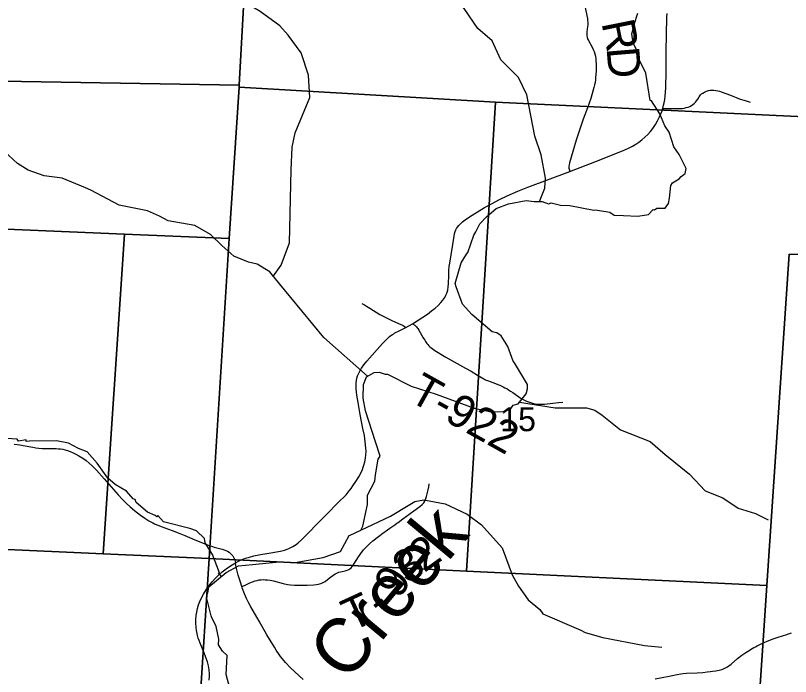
# Model space of a CAD drawing. Extents: x 0 to 34, y 0 to 22.
# Drawn here: x 25.758 to 27.11, y 16.507 to 17.66 of the extents above; entities that cross this region are included whole.
import ezdxf

# ---------------------------------------------------------------- set-up
doc = ezdxf.new("R2010")
doc.units = 0
for name, color, linetype in [('GM_X_County_Road', 7, 'Continuous'), ('GM_X_Minor_River', 7, 'Continuous'), ('GM_X_Minor_River_Text', 7, 'Continuous'), ('GM_X_Section', 7, 'Continuous'), ('GM_X_Section_Text', 7, 'Continuous'), ('GM_X_State_Route', 7, 'Continuous'), ('GM_X_Township_Road', 7, 'Continuous'), ('GM_X_Township_Road_Text', 7, 'Continuous')]:
    doc.layers.add(name, color=color, linetype=linetype)

msp = doc.modelspace()

# ---------------------------------------------------------------- linework, layer by layer
at = {"layer": 'GM_X_County_Road'}
for points in [[(25.7561, 16.9119), (25.7608, 16.9114), (25.7659, 16.9107), (25.7713, 16.9097), (25.7885, 16.9067), (25.7936, 16.9059), (25.799, 16.9052), (25.8046, 16.9048), (25.8103, 16.9046), (25.8291, 16.9044), (25.833, 16.9043), (25.8369, 16.9039), (25.8409, 16.9032), (25.8447, 16.9022), (25.8491, 16.901), (25.8535, 16.8993), (25.8586, 16.8971), (25.8633, 16.8947), (25.8686, 16.8917), (25.8753, 16.8875), (25.8813, 16.8834), (25.8868, 16.8792), (25.8921, 16.8742), (25.8992, 16.867), (25.913, 16.8518), (25.9373, 16.8238), (25.9449, 16.8156), (25.9511, 16.8094), (25.9579, 16.8031), (25.9656, 16.7966), (25.9759, 16.7886), (25.9836, 16.7832), (25.9909, 16.7784), (25.9975, 16.7748), (26.0007, 16.7732), (26.0044, 16.7716), (26.0081, 16.77), (26.0121, 16.7684), (26.0311, 16.7615), (26.0418, 16.7575), (26.0535, 16.7528), (26.074, 16.7442), (26.0957, 16.7355), (26.1019, 16.7334), (26.1044, 16.7325), (26.1071, 16.7318), (26.1188, 16.7288), (26.122, 16.7278), (26.1251, 16.7267), (26.1281, 16.7253), (26.1307, 16.7235), (26.1331, 16.7216), (26.1353, 16.7194), (26.1371, 16.7172), (26.1385, 16.7149), (26.1395, 16.713), (26.1403, 16.7108), (26.141, 16.7084), (26.1416, 16.7049)], [(26.8734, 16.5027), (26.8981, 16.5077), (26.912, 16.5104), (26.9181, 16.5114), (26.9224, 16.512), (26.9285, 16.5125), (26.9471, 16.5133), (26.9565, 16.5139), (26.9645, 16.5148), (26.97, 16.5156), (26.9738, 16.5161), (26.9794, 16.517), (26.985, 16.518), (26.9898, 16.5193), (26.9939, 16.5209), (26.9984, 16.5231), (27.0022, 16.5254), (27.0062, 16.5284), (27.0174, 16.5382), (27.0247, 16.5439), (27.0317, 16.5488), (27.0343, 16.5505), (27.0426, 16.5556), (27.0457, 16.5574), (27.0484, 16.5588), (27.0516, 16.5605), (27.0582, 16.5638), (27.069, 16.5684), (27.0795, 16.5724), (27.0882, 16.5754), (27.103, 16.5803), (27.1041, 16.5807), (27.1112, 16.5831)]]:
    msp.add_lwpolyline(points, dxfattribs=at)
at = {"layer": 'GM_X_Minor_River'}
for points in [[(26.6717, 17.3353), (26.6812, 17.3584), (26.6822, 17.3762), (26.6747, 17.417), (26.664, 17.4496), (26.6499, 17.5215), (26.635, 17.5519), (26.6181, 17.5692), (26.6045, 17.5825), (26.5893, 17.6157), (26.5642, 17.637), (26.5403, 17.6723), (26.4513, 17.7909), (26.4148, 17.8437), (26.3814, 17.8649), (26.3697, 17.8778), (26.3662, 17.887), (26.3625, 17.8917), (26.2809, 17.9664), (26.2609, 18.0039)], [(26.2068, 17.204), (26.2214, 17.2242), (26.236, 17.2634), (26.2386, 17.3906), (26.2407, 17.4301), (26.2458, 17.4552), (26.2716, 17.5168), (26.2691, 17.5559), (26.2564, 17.5946), (26.2338, 17.6256), (26.2189, 17.6418), (26.185, 17.6671), (26.0772, 17.7307), (26.0349, 17.7505), (25.925, 17.7982), (25.8376, 17.8672), (25.8216, 17.8773), (25.7426, 17.8997), (25.7266, 17.9076), (25.6949, 17.9317)], [(26.8364, 17.6413), (26.8368, 17.6439), (26.8432, 17.6637)], [(26.547, 17.2463), (26.5574, 17.2765), (26.5608, 17.2826), (26.5679, 17.2967), (26.5793, 17.3089), (26.5963, 17.3234), (26.6178, 17.3314), (26.6484, 17.3372), (26.6624, 17.3353), (26.6764, 17.3353), (26.6874, 17.3312), (26.6923, 17.3331), (26.7085, 17.3289), (26.7248, 17.3286), (26.7668, 17.3203), (26.7694, 17.3211), (26.7944, 17.317), (26.8023, 17.3117), (26.8186, 17.311), (26.8435, 17.3099), (26.862, 17.313), (26.8703, 17.3213), (26.8726, 17.3206), (26.8764, 17.3236), (26.8911, 17.3237), (26.8968, 17.3317), (26.8987, 17.3412), (26.9009, 17.3632), (26.9039, 17.3682), (26.9157, 17.375), (26.9191, 17.3788), (26.9259, 17.3842), (26.9274, 17.3929), (26.9152, 17.4172), (26.9062, 17.4309), (26.8978, 17.4563), (26.8906, 17.4673), (26.8819, 17.4882), (26.8671, 17.511), (26.8649, 17.5114), (26.8573, 17.5592), (26.8425, 17.5892), (26.8406, 17.601), (26.8353, 17.612), (26.833, 17.6276), (26.8364, 17.6413)], [(26.3718, 17.0307), (26.2957, 17.098), (26.2192, 17.1912), (26.2017, 17.2126), (26.1798, 17.2262), (26.1644, 17.2294), (26.1387, 17.24), (26.1177, 17.2586), (26.0982, 17.2778), (26.0711, 17.2934), (26.0241, 17.3018), (26.0092, 17.3098), (25.9884, 17.3192), (25.9388, 17.3288), (25.8893, 17.355), (25.88, 17.3595), (25.8396, 17.3759), (25.8084, 17.38), (25.78, 17.3903), (25.7618, 17.4019), (25.7313, 17.4298)], [(26.3246, 16.7249), (26.3397, 16.7527), (26.342, 16.7534), (26.3605, 16.7622), (26.3639, 16.7694), (26.3722, 16.8067), (26.3722, 16.8234), (26.3846, 16.8474), (26.3861, 16.8588), (26.3907, 16.8858), (26.3941, 16.8911), (26.3857, 16.9162), (26.3683, 16.9705), (26.3645, 16.9921), (26.3648, 17.0161), (26.3701, 17.0298), (26.3833, 17.037), (26.3924, 17.0378), (26.403, 17.034), (26.4071, 17.0341), (26.448, 17.0133), (26.4919, 16.9993), (26.5577, 16.9751), (26.5875, 16.9688), (26.6087, 16.9692), (26.6212, 16.9734), (26.6257, 16.9799), (26.6344, 16.9825), (26.6487, 16.9997), (26.651, 17.0084), (26.651, 17.016), (26.6283, 17.054), (26.626, 17.057), (26.6165, 17.0825), (26.6052, 17.101), (26.5976, 17.1064), (26.5893, 17.1082), (26.5541, 17.1385), (26.5375, 17.1564), (26.5265, 17.1867), (26.5249, 17.1924), (26.5355, 17.2286), (26.5446, 17.2434), (26.547, 17.2463)], [(26.6369, 16.9856), (26.6991, 16.9758), (26.7539, 16.9756), (26.7682, 16.9713), (26.7811, 16.9626), (26.8132, 16.9369), (26.8648, 16.9166), (26.8913, 16.8941), (26.9337, 16.8597), (26.9608, 16.8308), (26.9915, 16.8188), (27.0181, 16.8005), (27.0485, 16.7912), (27.0704, 16.7802)], [(26.1171, 16.6813), (26.1119, 16.6875), (26.1141, 16.6875), (26.1016, 16.7197), (26.0891, 16.7402), (26.0876, 16.7474), (26.074, 16.7607), (26.0619, 16.7649), (26.0161, 16.7769), (26.0063, 16.7875), (26.0044, 16.7852), (26.0018, 16.7875), (25.9882, 16.7935), (25.9685, 16.8102), (25.9666, 16.8155), (25.9636, 16.817), (25.9515, 16.8303), (25.9318, 16.842), (25.9193, 16.8527), (25.9004, 16.8788), (25.883, 16.8989), (25.8682, 16.9046), (25.8505, 16.9137), (25.8297, 16.9182), (25.7828, 16.9173), (25.7767, 16.9169), (25.7767, 16.9195), (25.7635, 16.9172), (25.7612, 16.9206), (25.7423, 16.9221)], [(26.3605, 16.7622), (26.4122, 16.7868), (26.446, 16.8069), (26.4545, 16.812), (26.4701, 16.8149), (26.5073, 16.808), (26.5457, 16.7901), (26.5705, 16.7715), (26.6067, 16.7312), (26.6245, 16.6843), (26.6352, 16.6642), (26.6519, 16.6409), (26.6726, 16.6239), (26.6776, 16.6162), (26.744, 16.5875), (26.7515, 16.5838), (26.7822, 16.5749), (26.8551, 16.5608), (26.8853, 16.5578)], [(26.147, 16.7001), (26.1712, 16.7024), (26.2181, 16.7071), (26.246, 16.706), (26.2944, 16.7142), (26.3246, 16.7249)], [(26.1317, 16.4865), (26.1253, 16.5104), (26.1271, 16.5435), (26.1192, 16.551), (26.112, 16.562), (26.1127, 16.5723), (26.1078, 16.594), (26.0998, 16.6107), (26.0991, 16.6126), (26.0915, 16.6452), (26.0941, 16.6555), (26.0953, 16.6631), (26.1255, 16.6883), (26.147, 16.7001)]]:
    msp.add_lwpolyline(points, dxfattribs=at)
at = {"layer": 'GM_X_Section'}
for points in [[(26.2062, 18.5294), (27.254, 18.479), (27.228, 18.0601), (27.2029, 17.6387), (27.1952, 17.4804), (26.5953, 17.5088), (26.1481, 17.5351), (26.1482, 17.5386), (26.1578, 17.7173), (26.1806, 18.1307)], [(25.1245, 17.7506), (26.1578, 17.7173), (26.1482, 17.5386), (25.1122, 17.5559)], [(26.1482, 17.5386), (26.1481, 17.5351), (26.131, 17.2706), (25.9484, 17.2784), (25.1664, 17.3116), (25.097, 17.3132), (25.1122, 17.5559)], [(26.5953, 17.5088), (26.5448, 16.6908), (26.0957, 16.7125), (26.131, 17.2706), (26.1481, 17.5351)], [(27.1952, 17.4804), (27.1786, 17.2427), (27.1074, 17.2433), (27.0684, 16.6654), (26.5448, 16.6908), (26.5953, 17.5088)], [(25.9484, 17.2784), (25.9113, 16.7209), (25.1282, 16.7564), (25.1664, 17.3116)], [(26.131, 17.2706), (26.0957, 16.7125), (25.9113, 16.7209), (25.9484, 17.2784)], [(27.1786, 17.2427), (27.1198, 16.4014), (27.0508, 16.4046), (27.0684, 16.6654), (27.1074, 17.2433)], [(25.1282, 16.7564), (25.9113, 16.7209), (26.0957, 16.7125), (26.0791, 16.4497), (25.1102, 16.4936)], [(26.0957, 16.7125), (26.5448, 16.6908), (27.0684, 16.6654), (27.0508, 16.4046), (26.0791, 16.4497)]]:
    msp.add_lwpolyline(points, close=True, dxfattribs=at)
at = {"layer": 'GM_X_State_Route'}
for points in [[(26.1963, 16.7214), (26.2203, 16.7256), (26.227, 16.7273), (26.2306, 16.7285), (26.2359, 16.7305), (26.242, 16.7336), (26.2473, 16.7371), (26.2512, 16.7403), (26.2568, 16.7453), (26.2963, 16.7853), (26.325, 16.8142), (26.33, 16.8193), (26.3345, 16.824), (26.3401, 16.8308), (26.3433, 16.835), (26.3464, 16.8393), (26.3517, 16.8471), (26.3566, 16.855), (26.3602, 16.8616), (26.3631, 16.8679), (26.3646, 16.872), (26.3658, 16.8756), (26.3674, 16.8816), (26.3686, 16.8878), (26.3692, 16.8934), (26.3694, 16.8991), (26.3691, 16.9054), (26.3679, 16.9165), (26.3665, 16.927), (26.364, 16.9392), (26.3592, 16.9641), (26.3554, 16.9848), (26.3544, 16.9911), (26.3534, 16.9974), (26.3527, 17.0036), (26.3524, 17.0085), (26.3521, 17.0141), (26.3522, 17.0189), (26.3526, 17.023), (26.3534, 17.027), (26.3548, 17.0315), (26.3567, 17.036), (26.3589, 17.0406), (26.3615, 17.0449), (26.3654, 17.0504), (26.3708, 17.0571), (26.3982, 17.0879), (26.4019, 17.0919), (26.4054, 17.0953), (26.4081, 17.0978), (26.4105, 17.0998), (26.4129, 17.1016), (26.4155, 17.1034), (26.4176, 17.1048), (26.4198, 17.1061), (26.4222, 17.1073), (26.4248, 17.1086), (26.4389, 17.1157), (26.4507, 17.1222), (26.4765, 17.1391), (26.4837, 17.1445), (26.4897, 17.1494), (26.4951, 17.1543), (26.4998, 17.1591), (26.5034, 17.1632), (26.5067, 17.1679), (26.5087, 17.1718), (26.5102, 17.1753), (26.5119, 17.1807), (26.5127, 17.1863), (26.5131, 17.1919), (26.5135, 17.2067), (26.5137, 17.211), (26.5139, 17.2153), (26.5146, 17.2221), (26.5153, 17.2276), (26.523, 17.2748), (26.5239, 17.2795), (26.5249, 17.283), (26.5259, 17.2858), (26.5274, 17.2885), (26.529, 17.2909), (26.5312, 17.2934), (26.5336, 17.2961), (26.5376, 17.2999), (26.5424, 17.3037), (26.5496, 17.3086), (26.576, 17.3248), (26.588, 17.3314), (26.6023, 17.3387), (26.6157, 17.3452), (26.6339, 17.3532), (26.6517, 17.3603), (26.725, 17.3875), (26.7713, 17.4057), (26.8164, 17.4236), (26.8272, 17.4284), (26.8339, 17.4318), (26.8398, 17.4352), (26.845, 17.4387), (26.8505, 17.4429), (26.8558, 17.4474), (26.8607, 17.4522), (26.8652, 17.4574), (26.8694, 17.4629), (26.8739, 17.4697), (26.8776, 17.4762), (26.8811, 17.4829), (26.8836, 17.4886), (26.8856, 17.4937), (26.8869, 17.4979), (26.8883, 17.5033), (26.8892, 17.5075), (26.8902, 17.5132), (26.8909, 17.5193), (26.8914, 17.5255), (26.892, 17.5345), (26.8924, 17.5438), (26.8926, 17.5522), (26.8928, 17.5628), (26.893, 17.5878), (26.8935, 17.6358), (26.8938, 17.6469), (26.8942, 17.6567), (26.8945, 17.6634)], [(26.1416, 16.7049), (26.1482, 16.7086), (26.1532, 16.7109), (26.159, 16.7131), (26.1661, 16.7151), (26.1739, 16.7171), (26.1854, 16.7195), (26.1963, 16.7214)], [(26.0959, 16.5003), (26.0963, 16.5072), (26.0963, 16.5116), (26.0957, 16.5185), (26.0946, 16.5253), (26.0928, 16.5326), (26.0903, 16.5403), (26.0874, 16.5479), (26.0802, 16.5651), (26.0784, 16.5698), (26.0768, 16.574), (26.0756, 16.5782), (26.0747, 16.5819), (26.074, 16.587), (26.0733, 16.5931), (26.0729, 16.5999), (26.0729, 16.6066), (26.0734, 16.6134), (26.0742, 16.6189), (26.0756, 16.6255), (26.0775, 16.632), (26.0797, 16.6377), (26.0824, 16.6439), (26.0859, 16.6504), (26.0908, 16.6583), (26.0955, 16.665), (26.1012, 16.6723), (26.1068, 16.6785), (26.113, 16.6845), (26.1188, 16.6897), (26.1255, 16.6947), (26.1333, 16.6999), (26.1416, 16.7049)], [(26.2097, 16.5581), (26.1966, 16.5798), (26.1831, 16.6033), (26.1685, 16.6286), (26.1649, 16.6351), (26.1611, 16.6428), (26.1574, 16.6513), (26.1536, 16.6617), (26.1528, 16.664), (26.1503, 16.6717), (26.1467, 16.6838), (26.1434, 16.6954), (26.1427, 16.6979), (26.1422, 16.7003), (26.1416, 16.7049)], [(26.26, 16.5014), (26.2379, 16.5223), (26.229, 16.5315), (26.2237, 16.5375), (26.2203, 16.5416), (26.2177, 16.5453), (26.2127, 16.5531), (26.2097, 16.5581)]]:
    msp.add_lwpolyline(points, dxfattribs=at)
at = {"layer": 'GM_X_Township_Road'}
for points in [[(26.7509, 17.6762), (26.7553, 17.6548), (26.7558, 17.6512), (26.7561, 17.6475), (26.756, 17.6438), (26.7556, 17.6402), (26.7549, 17.6364), (26.7543, 17.6308), (26.7542, 17.6264), (26.7544, 17.6241), (26.7549, 17.6218), (26.7558, 17.6192), (26.7573, 17.6164), (26.7636, 17.6047), (26.7657, 17.6005), (26.7672, 17.5968), (26.7684, 17.5932), (26.7693, 17.5891), (26.7699, 17.5845), (26.7703, 17.5805), (26.7706, 17.5756), (26.7707, 17.5693), (26.7705, 17.5628), (26.7698, 17.5518), (26.7694, 17.5474), (26.7687, 17.5428), (26.7679, 17.5387), (26.7669, 17.5343), (26.7616, 17.5153), (26.7558, 17.4987), (26.7482, 17.4792), (26.7359, 17.4425), (26.7244, 17.4027), (26.7236, 17.3996), (26.7232, 17.3973), (26.7231, 17.3955), (26.7232, 17.3937), (26.7238, 17.3916), (26.725, 17.3875)], [(26.8869, 17.4979), (26.9001, 17.4974), (26.9146, 17.4975), (26.9184, 17.4977), (26.9214, 17.4979), (26.9243, 17.4983), (26.9277, 17.4991), (26.9311, 17.5001), (26.9343, 17.5014), (26.9372, 17.5031), (26.9392, 17.5045), (26.9413, 17.5063), (26.9439, 17.5088), (26.9458, 17.5111), (26.9479, 17.514), (26.9502, 17.5178), (26.9515, 17.5199), (26.9528, 17.5215), (26.9545, 17.523), (26.9566, 17.5245), (26.9596, 17.5262), (26.963, 17.5277), (26.9664, 17.5289), (26.9693, 17.5295), (26.9727, 17.5298), (26.9758, 17.5297), (26.9792, 17.5293), (26.9827, 17.5287), (26.9857, 17.5277), (26.9887, 17.5267), (27.0048, 17.5207), (27.0217, 17.5142), (27.0304, 17.5113), (27.0392, 17.5087)], [(26.362, 17.1573), (26.3665, 17.155), (26.3704, 17.1529), (26.3763, 17.1494), (26.3936, 17.1384), (26.406, 17.1317), (26.4154, 17.127), (26.4301, 17.1209), (26.432, 17.1201), (26.4341, 17.119), (26.4359, 17.1178), (26.4389, 17.1157)], [(26.4507, 17.1222), (26.4543, 17.1196), (26.4564, 17.1178), (26.4576, 17.1166), (26.4588, 17.1153), (26.46, 17.1137), (26.4615, 17.1111), (26.4691, 17.0975), (26.4717, 17.0933), (26.4731, 17.0911), (26.4744, 17.0894), (26.4755, 17.0879), (26.4772, 17.0859), (26.479, 17.0839), (26.4806, 17.0822), (26.4826, 17.0806), (26.4846, 17.079), (26.4868, 17.0774), (26.4895, 17.0756), (26.5086, 17.0639), (26.5426, 17.0446), (26.553, 17.0394), (26.564, 17.0326), (26.5748, 17.0261), (26.5767, 17.025), (26.5787, 17.024), (26.5811, 17.023), (26.5951, 17.0179), (26.5993, 17.0164), (26.6025, 17.0152), (26.6061, 17.0135), (26.6087, 17.0122), (26.6116, 17.0107), (26.6147, 17.009), (26.618, 17.007), (26.6215, 17.0048), (26.6253, 17.0021), (26.6359, 16.9945), (26.6399, 16.992), (26.6443, 16.9897), (26.649, 16.9874), (26.6543, 16.9854), (26.6597, 16.9838), (26.6639, 16.9826), (26.667, 16.9821), (26.6699, 16.9819), (26.6744, 16.9819), (26.6805, 16.9822), (26.6952, 16.9837), (26.7052, 16.9848), (26.7124, 16.9855)], [(26.1528, 16.664), (26.1573, 16.6659), (26.1669, 16.67), (26.1763, 16.6735), (26.1796, 16.6745), (26.1832, 16.6753), (26.1866, 16.6758), (26.1899, 16.6759), (26.1933, 16.6758), (26.1975, 16.6754), (26.2022, 16.6748), (26.2083, 16.6735), (26.2251, 16.6691), (26.2324, 16.6676), (26.2379, 16.6669), (26.2446, 16.6664), (26.2521, 16.6663), (26.267, 16.6665), (26.2781, 16.6668), (26.283, 16.6673), (26.2866, 16.668), (26.2908, 16.6692), (26.2949, 16.671), (26.2979, 16.6727), (26.3024, 16.6759), (26.3076, 16.6804), (26.3116, 16.6833), (26.3153, 16.6857), (26.3187, 16.6873), (26.3222, 16.6886), (26.3277, 16.6899), (26.3331, 16.691), (26.3366, 16.6921), (26.3393, 16.6934), (26.3414, 16.6947), (26.3432, 16.6963), (26.3452, 16.6985), (26.348, 16.7026), (26.3561, 16.7158), (26.3601, 16.7214), (26.3652, 16.7278), (26.3702, 16.7333), (26.3756, 16.7385), (26.3813, 16.7434), (26.391, 16.7511), (26.3989, 16.7571), (26.4111, 16.7657), (26.4162, 16.7692), (26.4197, 16.7717), (26.4233, 16.7742), (26.4253, 16.7756), (26.4338, 16.7818), (26.4528, 16.7958), (26.4633, 16.8035), (26.4671, 16.8067), (26.47, 16.8098), (26.4719, 16.8129), (26.4732, 16.8157), (26.475, 16.8209), (26.4776, 16.8324), (26.4788, 16.8377), (26.4797, 16.8429)]]:
    msp.add_lwpolyline(points, dxfattribs=at)

# ---------------------------------------------------------------- texts
at = {"layer": 'GM_X_Minor_River_Text'}
msp.add_text('Creek', height=0.0947, rotation=50.1344, dxfattribs=at).set_placement((26.3355, 16.4945))
at = {"layer": 'GM_X_Section_Text'}
msp.add_text('15', height=0.04186, rotation=0, dxfattribs=at).set_placement((26.6034, 16.9348))
at = {"layer": 'GM_X_Township_Road_Text'}
for s, height, rotation, p in [('R', 0.0568, 281.2384, (26.7798, 17.6471)), ('D', 0.0568, 274.719, (26.7887, 17.603)), ('T-922', 0.05682, 330.8119, (26.4414, 16.9894)), ('2', 0.0568, 35.3991, (26.4707, 16.6871)), ('3', 0.0568, 36.3172, (26.4427, 16.6665)), ('9', 0.0568, 58.8682, (26.4285, 16.6409)), ('T', 0.0568, 24.7018, (26.3443, 16.5846)), ('-', 0.0568, 37.6277, (26.3948, 16.6096))]:
    msp.add_text(s, height=height, rotation=rotation, dxfattribs=at).set_placement(p)

doc.saveas('drawing.dxf')
